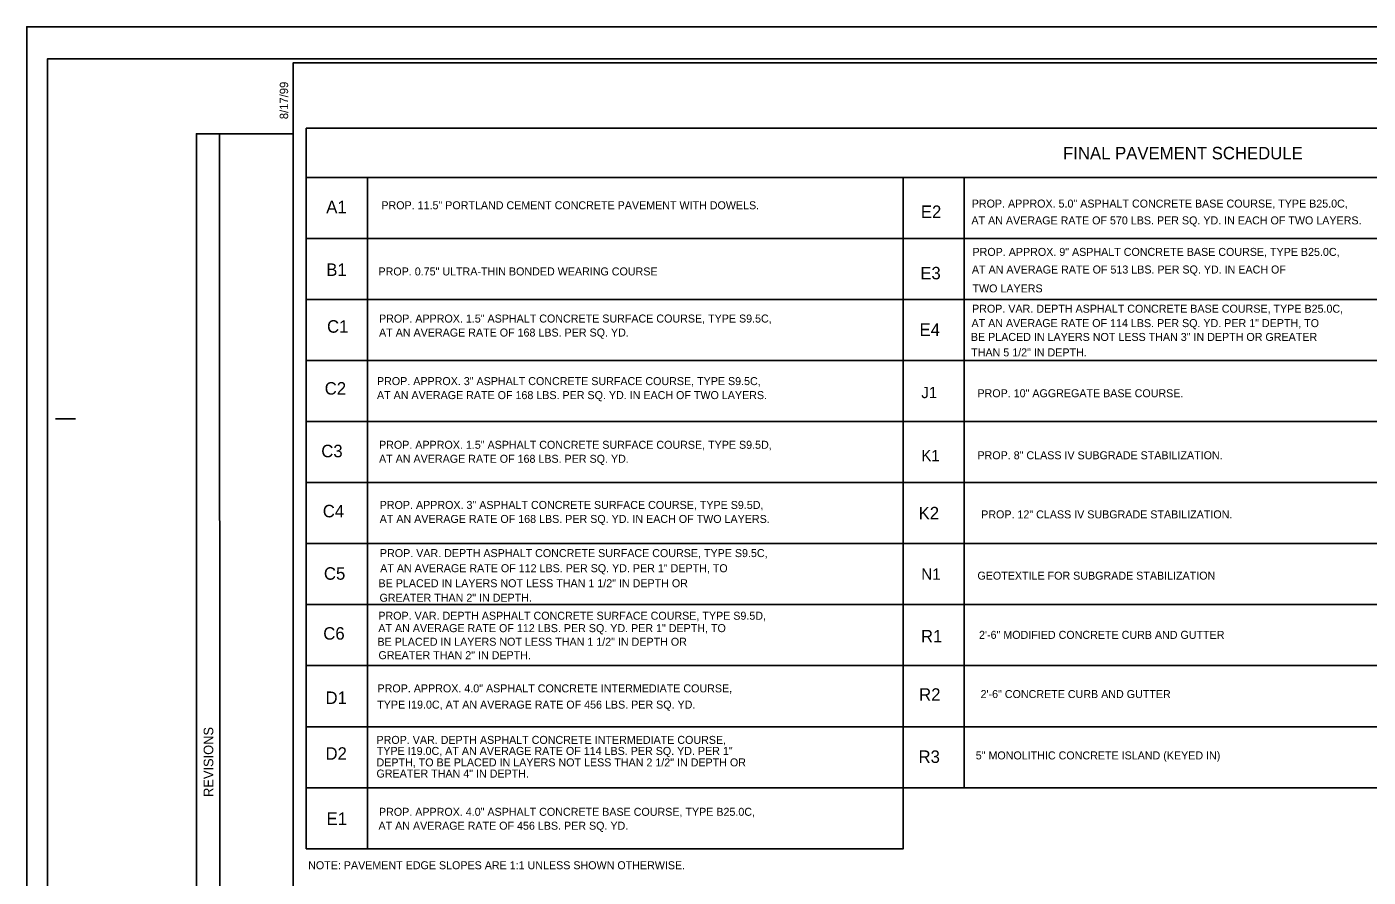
# Model space of a CAD drawing. Extents: x 1640342 to 1730599, y 538663 to 843747.
# Drawn here: x 1729840.7 to 1730008.3, y 540249.6 to 540355.9 of the extents above; entities that cross this region are included whole.
import ezdxf

# ---------------------------------------------------------------- set-up
doc = ezdxf.new("R2010")
doc.units = 0
for name, color, linetype in [('Default', 7, 'Continuous'), ('Prop Pavement Schedule Description CELL', 7, 'Continuous'), ('Sheet Block Revision CELL', 7, 'Continuous'), ('Sheet Plan CELL', 7, 'Continuous'), ('Sheet Plot Border Inside CELL', 7, 'Continuous'), ('Sheet Plot Border Outside CELL', 7, 'Continuous')]:
    doc.layers.add(name, color=color, linetype=linetype)

msp = doc.modelspace()

# ---------------------------------------------------------------- linework, layer by layer
at = {"layer": 'Default'}
for p, q in [((1729875.62, 540337.1), (1729875.62, 540343.23)), ((1729875.62, 540343.23), (1730099.44, 540343.23)), ((1729875.62, 540337.1), (1730013.83, 540337.1))]:
    msp.add_line(p, q, dxfattribs=at)
at = {"layer": 'Prop Pavement Schedule Description CELL'}
for points in [[(1729883.25, 540329.47), (1729875.62, 540329.47), (1729875.62, 540337.1), (1729950.22, 540337.1), (1729950.22, 540329.47), (1729883.25, 540329.47), (1729883.25, 540337.1)], [(1729957.85, 540329.47), (1729950.22, 540329.47), (1729950.22, 540337.1), (1730024.83, 540337.1), (1730024.83, 540329.47), (1729957.85, 540329.47), (1729957.85, 540337.1)], [(1729883.25, 540321.84), (1729875.62, 540321.84), (1729875.62, 540329.47), (1729950.22, 540329.47), (1729950.22, 540321.84), (1729883.25, 540321.84), (1729883.25, 540329.47)], [(1729957.85, 540321.84), (1729950.22, 540321.84), (1729950.22, 540329.47), (1730024.83, 540329.47), (1730024.83, 540321.84), (1729957.85, 540321.84), (1729957.85, 540329.47)], [(1729883.25, 540314.21), (1729875.62, 540314.21), (1729875.62, 540321.84), (1729950.22, 540321.84), (1729950.22, 540314.21), (1729883.25, 540314.21), (1729883.25, 540321.84)], [(1729957.85, 540314.21), (1729950.22, 540314.21), (1729950.22, 540321.84), (1730024.83, 540321.84), (1730024.83, 540314.21), (1729957.85, 540314.21), (1729957.85, 540321.84)], [(1729883.25, 540306.58), (1729875.62, 540306.58), (1729875.62, 540314.21), (1729950.22, 540314.21), (1729950.22, 540306.58), (1729883.25, 540306.58), (1729883.25, 540314.21)], [(1729957.85, 540306.58), (1729950.22, 540306.58), (1729950.22, 540314.21), (1730024.83, 540314.21), (1730024.83, 540306.58), (1729957.85, 540306.58), (1729957.85, 540314.21)], [(1729883.25, 540298.95), (1729875.62, 540298.95), (1729875.62, 540306.58), (1729950.22, 540306.58), (1729950.22, 540298.95), (1729883.25, 540298.95), (1729883.25, 540306.58)], [(1729957.85, 540298.95), (1729950.22, 540298.95), (1729950.22, 540306.58), (1730024.83, 540306.58), (1730024.83, 540298.95), (1729957.85, 540298.95), (1729957.85, 540306.58)], [(1729883.25, 540291.32), (1729875.62, 540291.32), (1729875.62, 540298.95), (1729950.22, 540298.95), (1729950.22, 540291.32), (1729883.25, 540291.32), (1729883.25, 540298.95)], [(1729957.85, 540291.32), (1729950.22, 540291.32), (1729950.22, 540298.95), (1730024.83, 540298.95), (1730024.83, 540291.32), (1729957.85, 540291.32), (1729957.85, 540298.95)], [(1729883.25, 540283.69), (1729875.62, 540283.69), (1729875.62, 540291.32), (1729950.22, 540291.32), (1729950.22, 540283.69), (1729883.25, 540283.69), (1729883.25, 540291.32)], [(1729957.85, 540283.69), (1729950.22, 540283.69), (1729950.22, 540291.32), (1730024.83, 540291.32), (1730024.83, 540283.69), (1729957.85, 540283.69), (1729957.85, 540291.32)], [(1729883.25, 540276.06), (1729875.62, 540276.06), (1729875.62, 540283.69), (1729950.22, 540283.69), (1729950.22, 540276.06), (1729883.25, 540276.06), (1729883.25, 540283.69)], [(1729957.85, 540276.06), (1729950.22, 540276.06), (1729950.22, 540283.69), (1730024.83, 540283.69), (1730024.83, 540276.06), (1729957.85, 540276.06), (1729957.85, 540283.69)], [(1729883.25, 540268.43), (1729875.62, 540268.43), (1729875.62, 540276.06), (1729950.22, 540276.06), (1729950.22, 540268.43), (1729883.25, 540268.43), (1729883.25, 540276.06)], [(1729957.85, 540268.43), (1729950.22, 540268.43), (1729950.22, 540276.06), (1730024.83, 540276.06), (1730024.83, 540268.43), (1729957.85, 540268.43), (1729957.85, 540276.06)], [(1729883.25, 540260.8), (1729875.62, 540260.8), (1729875.62, 540268.43), (1729950.22, 540268.43), (1729950.22, 540260.8), (1729883.25, 540260.8), (1729883.25, 540268.43)], [(1729957.85, 540260.8), (1729950.22, 540260.8), (1729950.22, 540268.43), (1730024.83, 540268.43), (1730024.83, 540260.8), (1729957.85, 540260.8), (1729957.85, 540268.43)], [(1729883.25, 540253.17), (1729875.62, 540253.17), (1729875.62, 540260.8), (1729950.22, 540260.8), (1729950.22, 540253.17), (1729883.25, 540253.17), (1729883.25, 540260.8)]]:
    msp.add_lwpolyline(points, dxfattribs=at)
at = {"layer": 'Sheet Block Revision CELL'}
msp.add_line((1729864.8, 540184.42), (1729864.79, 540342.55), dxfattribs=at)
msp.add_lwpolyline([(1729861.89, 540184.41), (1729861.89, 540342.54), (1729873.99, 540342.55), (1729873.99, 540184.42)], close=True, dxfattribs=at)
at = {"layer": 'Sheet Plan CELL'}
for p, q in [((1729873.99, 540351.42), (1729873.99, 540351.42)), ((1729844.29, 540306.91), (1729846.79, 540306.92))]:
    msp.add_line(p, q, dxfattribs=at)
for points in [[(1730174, 540351.42), (1729873.99, 540351.42), (1729873.99, 540141.42), (1730173.99, 540141.42)], [(1729873.99, 540141.42), (1729873.99, 540351.41), (1730133.98, 540351.42), (1730133.99, 540321.41), (1730173.99, 540321.41), (1730173.99, 540141.42)]]:
    msp.add_lwpolyline(points, close=True, dxfattribs=at)
at = {"layer": 'Sheet Plot Border Inside CELL'}
msp.add_lwpolyline([(1729843.29, 540140.92), (1730176.49, 540140.92), (1730176.49, 540351.92), (1729843.29, 540351.92)], close=True, dxfattribs=at)
at = {"layer": 'Sheet Plot Border Outside CELL'}
msp.add_lwpolyline([(1729840.69, 540136.92), (1730177.39, 540136.92), (1730177.39, 540355.92), (1729840.69, 540355.92)], close=True, dxfattribs=at)

# ---------------------------------------------------------------- texts
at = {"layer": 'Default'}
for s, height, p in [('FINAL PAVEMENT SCHEDULE', 1.5625, (1729970.19, 540339.35)), ('A1', 1.562, (1729878.11, 540332.62)), ('PROP. 11.5" PORTLAND CEMENT CONCRETE PAVEMENT WITH DOWELS.', 1, (1729885, 540333.11)), ('E2', 1.562, (1729952.42, 540332.02)), ('PROP. APPROX. 5.0" ASPHALT CONCRETE BASE COURSE, TYPE B25.0C,', 1, (1729958.78, 540333.32)), ('AT AN AVERAGE RATE OF 570 LBS. PER SQ. YD. IN EACH OF TWO LAYERS.', 1, (1729958.74, 540331.22)), ('PROP. APPROX. 9" ASPHALT CONCRETE BASE COURSE, TYPE B25.0C,', 1, (1729958.87, 540327.28)), ('B1', 1.562, (1729878.11, 540324.78)), ('PROP. 0.75" ULTRA-THIN BONDED WEARING COURSE', 1, (1729884.64, 540324.84)), ('E3', 1.562, (1729952.35, 540324.35)), ('AT AN AVERAGE RATE OF 513 LBS. PER SQ. YD. IN EACH OF', 1, (1729958.8, 540325.08)), ('TWO LAYERS', 1, (1729958.87, 540322.72)), ('PROP. APPROX. 1.5" ASPHALT CONCRETE SURFACE COURSE, TYPE S9.5C,', 1, (1729884.71, 540318.95)), ('PROP. VAR. DEPTH ASPHALT CONCRETE BASE COURSE, TYPE B25.0C,', 1, (1729958.82, 540320.18)), ('C1', 1.562, (1729878.21, 540317.68)), ('AT AN AVERAGE RATE OF 168 LBS. PER SQ. YD.', 1, (1729884.71, 540317.2)), ('E4', 1.562, (1729952.25, 540317.28)), ('AT AN AVERAGE RATE OF 114 LBS. PER SQ. YD. PER 1" DEPTH, TO', 1, (1729958.75, 540318.38)), ('BE PLACED IN LAYERS NOT LESS THAN 3" IN DEPTH OR GREATER', 1, (1729958.67, 540316.65)), ('THAN 5 1/2" IN DEPTH.', 1, (1729958.71, 540314.72)), ('C2', 1.562, (1729877.92, 540309.94)), ('PROP. APPROX. 3" ASPHALT CONCRETE SURFACE COURSE, TYPE S9.5C,', 1, (1729884.45, 540311.13)), ('AT AN AVERAGE RATE OF 168 LBS. PER SQ. YD. IN EACH OF TWO LAYERS.', 1, (1729884.45, 540309.38)), ('PROP. 10" AGGREGATE BASE COURSE.', 1, (1729959.49, 540309.61)), ('C3', 1.562, (1729877.49, 540302.11)), ('PROP. APPROX. 1.5" ASPHALT CONCRETE SURFACE COURSE, TYPE S9.5D,', 1, (1729884.71, 540303.17)), ('AT AN AVERAGE RATE OF 168 LBS. PER SQ. YD.', 1, (1729884.71, 540301.42)), ('PROP. 8" CLASS IV SUBGRADE STABILIZATION.', 1, (1729959.49, 540301.86)), ('PROP. APPROX. 3" ASPHALT CONCRETE SURFACE COURSE, TYPE S9.5D,', 1, (1729884.79, 540295.65)), ('C4', 1.562, (1729877.68, 540294.6)), ('AT AN AVERAGE RATE OF 168 LBS. PER SQ. YD. IN EACH OF TWO LAYERS.', 1, (1729884.79, 540293.9)), ('K2', 1.562, (1729952.14, 540294.35)), ('PROP. 12" CLASS IV SUBGRADE STABILIZATION.', 1, (1729959.96, 540294.47)), ('PROP. VAR. DEPTH ASPHALT CONCRETE SURFACE COURSE, TYPE S9.5C,', 1, (1729884.82, 540289.63)), ('C5', 1.562, (1729877.82, 540286.8)), ('AT AN AVERAGE RATE OF 112 LBS. PER SQ. YD. PER 1" DEPTH, TO', 1, (1729884.85, 540287.74)), ('BE PLACED IN LAYERS NOT LESS THAN 1 1/2" IN DEPTH OR', 1, (1729884.64, 540285.86)), ('GEOTEXTILE FOR SUBGRADE STABILIZATION', 1, (1729959.49, 540286.81)), ('GREATER THAN 2" IN DEPTH.', 1, (1729884.77, 540284.05)), ('AT AN AVERAGE RATE OF 112 LBS. PER SQ. YD. PER 1" DEPTH, TO', 1, (1729884.62, 540280.25)), ('PROP. VAR. DEPTH ASPHALT CONCRETE SURFACE COURSE, TYPE S9.5D,', 1, (1729884.62, 540281.8)), ('C6', 1.562, (1729877.74, 540279.31)), ('BE PLACED IN LAYERS NOT LESS THAN 1 1/2" IN DEPTH OR', 1, (1729884.51, 540278.55)), ('R1', 1.562, (1729952.43, 540278.96)), ('2\'-6" MODIFIED CONCRETE CURB AND GUTTER', 1, (1729959.69, 540279.41)), ('GREATER THAN 2" IN DEPTH.', 1, (1729884.64, 540276.87)), ('PROP. APPROX. 4.0" ASPHALT CONCRETE INTERMEDIATE COURSE,', 1, (1729884.52, 540272.72)), ('R2', 1.562, (1729952.2, 540271.67)), ('2\'-6" CONCRETE CURB AND GUTTER', 1, (1729959.88, 540272.01)), ('D1', 1.562, (1729878.02, 540271.27)), ('TYPE I19.0C, AT AN AVERAGE RATE OF 456 LBS. PER SQ. YD.', 1, (1729884.48, 540270.69)), ('PROP. VAR. DEPTH ASPHALT CONCRETE INTERMEDIATE COURSE,', 1, (1729884.39, 540266.28)), ('D2', 1.562, (1729878.02, 540264.3)), ('TYPE I19.0C, AT AN AVERAGE RATE OF 114 LBS. PER SQ. YD. PER 1" ', 1, (1729884.43, 540264.9)), ('DEPTH, TO BE PLACED IN LAYERS NOT LESS THAN 2 1/2" IN DEPTH OR', 1, (1729884.39, 540263.47)), ('R3', 1.562, (1729952.13, 540263.9)), ('5" MONOLITHIC CONCRETE ISLAND (KEYED IN)', 1, (1729959.28, 540264.34)), ('GREATER THAN 4" IN DEPTH.', 1, (1729884.39, 540262.07)), ('PROP. APPROX. 4.0" ASPHALT CONCRETE BASE COURSE, TYPE B25.0C,', 1, (1729884.7, 540257.29)), ('E1', 1.562, (1729878.15, 540256.15)), ('AT AN AVERAGE RATE OF 456 LBS. PER SQ. YD.', 1, (1729884.64, 540255.55)), ('NOTE: PAVEMENT EDGE SLOPES ARE 1:1 UNLESS SHOWN OTHERWISE.', 1, (1729875.85, 540250.61))]:
    msp.add_text(s, height=height, dxfattribs=at).set_placement(p)
at = {"layer": 'Prop Pavement Schedule Description CELL'}
for s, p in [('J1', (1729952.47, 540309.5)), ('K1', (1729952.47, 540301.62)), ('N1', (1729952.47, 540286.8))]:
    msp.add_text(s, height=1.413, dxfattribs=at).set_placement(p)
at = {"layer": 'Sheet Block Revision CELL'}
msp.add_text('REVISIONS', height=1.2, rotation=90, dxfattribs=at).set_placement((1729863.99, 540259.65))
at = {"layer": 'Sheet Plan CELL'}
msp.add_text('8/17/99', height=1.05, rotation=90, dxfattribs=at).set_placement((1729873.35, 540344.37))

doc.saveas('drawing.dxf')
